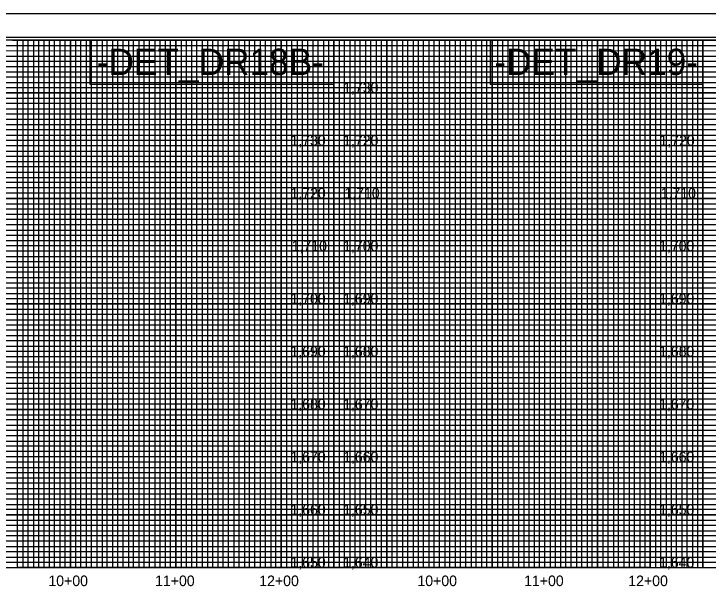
# Model space of a CAD drawing. Extents: x 505692 to 527456, y 415959 to 439886.
# Drawn here: x 506355 to 507014, y 439315 to 439861 of the extents above; entities that cross this region are included whole.
import ezdxf

# ---------------------------------------------------------------- set-up
doc = ezdxf.new("R2010")
doc.units = 0
for name, color, linetype in [('Exist Vertical Profile Vertical Axis Label', 7, 'Continuous'), ('Old_Level_1', 7, 'Continuous'), ('Prop Grid Mask', 7, 'Continuous'), ('Sheet Cutting Line CELL', 7, 'Continuous'), ('Sheet DOT Grid CELL', 7, 'Continuous'), ('Sheet Layout Profile Border Port 1', 7, 'Continuous'), ('Sheet Layout Profile Border Port 2', 7, 'Continuous'), ('Sheet Plot Border Inside CELL', 7, 'Continuous'), ('Sheet Plot Border Outside CELL', 7, 'Continuous'), ('Sheet Profile CELL', 7, 'Continuous'), ('Sheet Profile Grid Major CELL', 7, 'Continuous'), ('Sheet Profile Grid Middle CELL', 7, 'Continuous'), ('Sheet Profile Grid Minor CELL', 7, 'Continuous')]:
    doc.layers.add(name, color=color, linetype=linetype)

msp = doc.modelspace()

# ---------------------------------------------------------------- linework, layer by layer
at = {"layer": 'Prop Grid Mask'}
for points in [[(506658.68, 439836.14), (506427.08, 439836.14), (506427.08, 439794.44), (506658.68, 439794.44)], [(507008.68, 439836.14), (506806.91, 439836.14), (506806.91, 439794.44), (507008.68, 439794.44)]]:
    msp.add_lwpolyline(points, close=True, dxfattribs=at)
at = {"layer": 'Sheet Cutting Line CELL'}
msp.add_line((507375.68, 439861.14), (505691.68, 439861.14), dxfattribs=at)
at = {"layer": 'Sheet DOT Grid CELL'}
for p, q in [((506358.68, 439336.14), (506358.68, 439836.14)), ((506408.68, 439336.14), (506408.68, 439836.14)), ((506458.68, 439336.14), (506458.68, 439836.14)), ((506508.68, 439336.14), (506508.68, 439836.14)), ((506558.68, 439336.14), (506558.68, 439836.14)), ((506608.68, 439336.14), (506608.68, 439836.14)), ((506658.68, 439336.14), (506658.68, 439836.14)), ((506708.68, 439336.14), (506708.68, 439836.14)), ((506758.68, 439336.14), (506758.68, 439836.14)), ((506808.68, 439336.14), (506808.68, 439836.14)), ((506858.68, 439336.14), (506858.68, 439836.14)), ((506908.68, 439336.14), (506908.68, 439836.14)), ((506958.68, 439336.14), (506958.68, 439836.14)), ((507008.68, 439336.14), (507008.68, 439836.14)), ((507158.63, 439786.14), (505858.68, 439786.14)), ((507158.63, 439736.14), (505858.68, 439736.14)), ((507158.68, 439686.14), (505858.68, 439686.14)), ((507358.68, 439636.14), (505858.68, 439636.14)), ((507358.68, 439586.14), (505858.68, 439586.14)), ((507358.68, 439536.14), (505858.68, 439536.14)), ((507358.68, 439486.14), (505858.68, 439486.14)), ((507358.68, 439436.14), (505858.68, 439436.14)), ((507358.68, 439386.14), (505858.68, 439386.14))]:
    msp.add_line(p, q, dxfattribs=at)
at = {"layer": 'Sheet Layout Profile Border Port 1'}
msp.add_lwpolyline([(506708.68, 439836.14), (506958.68, 439836.14), (506958.68, 439336.14), (506708.68, 439336.14)], close=True, dxfattribs=at)
at = {"layer": 'Sheet Layout Profile Border Port 2'}
msp.add_lwpolyline([(506358.68, 439836.14), (506708.68, 439836.14), (506708.68, 439336.14), (506358.68, 439336.14)], close=True, dxfattribs=at)
at = {"layer": 'Sheet Plot Border Inside CELL'}
msp.add_lwpolyline([(505704.68, 438783.59), (507371.18, 438783.59), (507371.18, 439838.69), (505704.68, 439838.69)], close=True, dxfattribs=at)
at = {"layer": 'Sheet Plot Border Outside CELL'}
msp.add_lwpolyline([(505691.68, 438761.14), (507375.68, 438761.14), (507375.68, 439861.14), (505691.68, 439861.14)], close=True, dxfattribs=at)
at = {"layer": 'Sheet Profile CELL'}
for p, q in [((506658.68, 439836.14), (506658.68, 439336.14)), ((507008.68, 439836.14), (507008.68, 439336.14)), ((505858.68, 439336.14), (507358.68, 439336.14))]:
    msp.add_line(p, q, dxfattribs=at)
msp.add_lwpolyline([(507358.68, 439836.14), (505858.68, 439836.14), (505858.68, 438786.14), (507358.68, 438786.14)], close=True, dxfattribs=at)
at = {"layer": 'Sheet Profile Grid Major CELL'}
for points in [[(506308.68, 439336.14), (506358.68, 439336.14), (506358.68, 439836.14), (506408.68, 439836.14), (506408.68, 439336.14), (506458.68, 439336.14), (506458.68, 439836.14), (506508.68, 439836.14), (506508.68, 439336.14), (506558.68, 439336.14), (506558.68, 439836.14), (506608.68, 439836.14), (506608.68, 439336.14), (506658.68, 439336.14), (506658.68, 439836.14), (506708.68, 439836.14), (506708.68, 439336.14), (506758.68, 439336.14), (506758.68, 439836.14), (506808.68, 439836.14), (506808.68, 439336.14), (506858.68, 439336.14), (506858.68, 439836.14), (506908.68, 439836.14), (506908.68, 439336.14), (506958.68, 439336.14), (506958.68, 439836.14), (507008.68, 439836.14), (507008.68, 439336.14), (507058.68, 439336.14)], [(505858.68, 439786.14), (507158.68, 439786.14)], [(507158.68, 439736.14), (505858.68, 439736.14), (505858.68, 439686.14), (507158.68, 439686.14)], [(507358.68, 439636.14), (505858.68, 439636.14), (505858.68, 439586.14), (507358.68, 439586.14)], [(507358.68, 439536.14), (505858.68, 439536.14), (505858.68, 439486.14), (507358.68, 439486.14)], [(507358.68, 439436.14), (505858.68, 439436.14), (505858.68, 439436.14), (505858.68, 439386.14), (507358.68, 439386.14)]]:
    msp.add_lwpolyline(points, dxfattribs=at)
at = {"layer": 'Sheet Profile Grid Middle CELL'}
msp.add_line((505858.68, 439811.14), (507158.63, 439811.14), dxfattribs=at)
for points in [[(506333.68, 439336.14), (506383.68, 439336.14), (506383.68, 439836.14), (506433.68, 439836.14), (506433.68, 439336.14), (506483.68, 439336.14), (506483.68, 439336.14), (506483.68, 439836.14), (506533.68, 439836.14), (506533.68, 439336.14), (506583.68, 439336.14), (506583.68, 439836.14), (506633.68, 439836.14), (506633.68, 439336.14), (506683.68, 439336.14), (506683.68, 439836.14), (506733.68, 439836.14), (506733.68, 439336.14), (506783.68, 439336.14), (506783.68, 439836.14), (506833.68, 439836.14), (506833.68, 439336.14), (506883.68, 439336.14), (506883.68, 439836.14), (506933.68, 439836.14), (506933.68, 439336.14), (506983.68, 439336.14), (506983.68, 439836.14), (507033.68, 439836.14)], [(507158.68, 439761.14), (505858.68, 439761.14), (505858.68, 439711.14), (507158.68, 439711.14)], [(507358.68, 439661.14), (505858.68, 439661.14), (505858.68, 439611.14), (507183.68, 439611.14)], [(507358.68, 439561.14), (505858.68, 439561.14), (505858.68, 439511.14), (507358.68, 439511.14)], [(507358.68, 439461.14), (505858.68, 439461.14), (505858.68, 439411.14), (507358.68, 439411.14)], [(507358.68, 439361.14), (505858.68, 439361.14)]]:
    msp.add_lwpolyline(points, dxfattribs=at)
at = {"layer": 'Sheet Profile Grid Minor CELL'}
for p, q in [((505908.68, 439831.14), (507158.68, 439831.14)), ((507158.68, 439826.14), (505908.68, 439825.79)), ((505908.68, 439821.14), (507158.68, 439821.14)), ((507158.63, 439701.14), (505908.68, 439701.14)), ((507158.68, 439696.14), (505908.68, 439696.14)), ((507158.68, 439691.14), (505908.68, 439691.14)), ((505908.68, 439681.14), (507158.68, 439681.14)), ((507158.68, 439676.14), (505908.68, 439676.14)), ((505908.68, 439671.14), (507308.68, 439671.14)), ((507308.68, 439651.14), (505908.68, 439651.14)), ((505908.68, 439646.14), (507308.68, 439646.14)), ((507308.68, 439626.14), (505908.68, 439626.14)), ((505908.68, 439621.14), (507308.68, 439621.14)), ((507308.68, 439601.14), (505908.68, 439601.14)), ((505908.68, 439596.14), (507308.68, 439596.14)), ((507308.68, 439591.14), (505908.68, 439591.14)), ((505908.68, 439581.14), (507308.68, 439581.14)), ((507308.68, 439576.14), (505908.68, 439576.14)), ((505908.68, 439571.14), (507308.68, 439571.14)), ((507308.68, 439566.14), (505908.68, 439566.14)), ((505908.68, 439556.14), (507308.68, 439556.14)), ((507308.68, 439551.14), (505908.68, 439551.14)), ((505908.68, 439546.14), (507308.68, 439546.14)), ((507308.68, 439541.14), (505908.68, 439541.14)), ((505908.68, 439531.14), (507308.68, 439531.14)), ((507308.68, 439526.14), (505908.68, 439526.14)), ((505908.68, 439521.14), (507308.68, 439521.14)), ((507308.68, 439516.14), (505908.68, 439516.14)), ((505908.68, 439506.14), (507308.68, 439506.14)), ((507308.68, 439501.14), (505908.68, 439501.14)), ((505908.68, 439496.14), (507308.68, 439496.14)), ((507308.68, 439491.14), (505908.68, 439491.14)), ((505908.68, 439481.14), (507308.68, 439481.14)), ((507308.68, 439476.14), (505908.68, 439476.14)), ((505908.68, 439471.14), (507308.68, 439471.14)), ((507308.68, 439466.14), (505908.68, 439466.14)), ((505908.68, 439456.14), (507308.68, 439456.14)), ((507308.68, 439451.14), (505908.68, 439451.14)), ((507308.68, 439446.14), (505908.68, 439446.14)), ((507308.68, 439441.14), (505908.68, 439441.14)), ((505908.68, 439431.14), (507308.68, 439431.14)), ((507308.68, 439426.14), (505908.68, 439426.14)), ((505908.68, 439421.14), (507308.68, 439421.14)), ((507308.68, 439416.14), (505908.68, 439416.14)), ((505908.68, 439406.14), (507308.68, 439406.14)), ((507308.68, 439401.14), (505908.68, 439401.14)), ((505908.68, 439396.14), (507308.68, 439396.14)), ((507308.68, 439391.14), (505908.68, 439391.14)), ((505908.68, 439381.14), (507308.68, 439381.14)), ((507308.68, 439376.14), (505908.68, 439376.14)), ((505908.68, 439371.14), (507308.68, 439371.14)), ((507308.68, 439366.14), (505908.68, 439366.14)), ((505908.68, 439356.14), (507308.68, 439356.14)), ((507308.68, 439351.14), (505908.68, 439351.14)), ((505908.68, 439346.14), (507308.68, 439346.14))]:
    msp.add_line(p, q, dxfattribs=at)
for points in [[(506353.68, 439836.14), (506363.68, 439836.14), (506363.68, 439336.14), (506368.68, 439336.14), (506368.68, 439836.14), (506373.68, 439836.14), (506373.68, 439336.14), (506378.68, 439336.14), (506378.68, 439836.14), (506388.68, 439836.14), (506388.68, 439336.14), (506393.68, 439336.14), (506393.68, 439836.14), (506398.68, 439836.14), (506398.68, 439336.14), (506403.68, 439336.14), (506403.68, 439836.14), (506413.68, 439836.14), (506413.68, 439336.14), (506418.68, 439336.14), (506418.68, 439836.14), (506423.68, 439836.14), (506423.68, 439336.14), (506428.68, 439336.14), (506428.68, 439836.14), (506438.68, 439836.14)], [(506438.68, 439836.14), (506438.68, 439336.14), (506443.68, 439336.14), (506443.68, 439836.14), (506448.68, 439836.14), (506448.68, 439336.14), (506453.68, 439336.14), (506453.68, 439836.14), (506463.68, 439836.14), (506463.68, 439336.14), (506468.68, 439336.14), (506468.68, 439836.14), (506473.68, 439836.14), (506473.68, 439336.14), (506478.68, 439336.14), (506478.68, 439836.14), (506488.68, 439836.14), (506488.68, 439336.14), (506493.68, 439336.14), (506493.68, 439836.14), (506498.68, 439836.14), (506498.68, 439336.14), (506503.68, 439336.14), (506503.68, 439836.14), (506513.68, 439836.14), (506513.68, 439336.14), (506518.68, 439336.14), (506518.68, 439836.14), (506523.68, 439836.14), (506523.68, 439336.14), (506528.68, 439336.14), (506528.68, 439836.14), (506538.68, 439836.14), (506538.68, 439336.14), (506543.68, 439336.14), (506543.68, 439836.14), (506548.68, 439836.14), (506548.68, 439336.14), (506553.68, 439336.14), (506553.68, 439836.14), (506563.68, 439836.14), (506563.68, 439336.14), (506563.68, 439336.14), (506568.68, 439336.14), (506568.68, 439836.14), (506573.68, 439836.14), (506573.68, 439336.14), (506578.68, 439336.14), (506578.68, 439836.14), (506588.68, 439836.14), (506588.68, 439336.14), (506593.68, 439336.14), (506593.68, 439836.14), (506598.68, 439836.14), (506598.68, 439336.14), (506603.68, 439336.14), (506603.68, 439836.14), (506613.68, 439836.14), (506613.68, 439336.14), (506618.68, 439336.14), (506618.68, 439836.14), (506623.68, 439836.14), (506623.68, 439336.14), (506628.68, 439336.14), (506628.68, 439836.14), (506638.68, 439836.14), (506638.68, 439336.14), (506643.68, 439336.14), (506643.68, 439836.14), (506648.68, 439836.14), (506648.68, 439336.14), (506653.68, 439336.14), (506653.68, 439836.14), (506663.68, 439836.14), (506663.68, 439336.14), (506668.68, 439336.14), (506668.68, 439836.14), (506673.68, 439836.14), (506673.68, 439336.14), (506678.68, 439336.14), (506678.68, 439836.14), (506688.68, 439836.14), (506688.68, 439336.14), (506693.68, 439336.14), (506693.68, 439836.14), (506698.68, 439836.14), (506698.68, 439336.14), (506703.68, 439336.14), (506703.68, 439836.14), (506713.68, 439836.14), (506713.68, 439336.14), (506717.37, 439336.14), (506718.68, 439336.14), (506718.68, 439836.14), (506723.68, 439836.14), (506723.68, 439336.14), (506728.68, 439336.14), (506728.68, 439836.14), (506738.68, 439836.14), (506738.68, 439336.14), (506743.68, 439336.14)], [(506743.68, 439336.14), (506743.68, 439836.14), (506748.68, 439836.14), (506748.68, 439336.14), (506753.68, 439336.14), (506753.68, 439836.14), (506763.68, 439836.14), (506763.68, 439336.14), (506768.68, 439336.14), (506768.68, 439836.14), (506773.68, 439836.14), (506773.68, 439336.14), (506778.68, 439336.14), (506778.68, 439836.14), (506788.68, 439836.14), (506788.68, 439336.14), (506793.68, 439336.14), (506793.68, 439836.14), (506798.68, 439836.14), (506798.68, 439336.14), (506803.68, 439336.14), (506803.68, 439836.14), (506813.68, 439836.14), (506813.68, 439336.14), (506818.68, 439336.14), (506818.68, 439836.14), (506823.68, 439836.14), (506823.68, 439336.14), (506828.68, 439336.14), (506828.68, 439836.14), (506838.68, 439836.14), (506838.68, 439336.14), (506843.68, 439336.14), (506843.68, 439836.14), (506848.68, 439836.14), (506848.68, 439336.14), (506853.68, 439336.14), (506853.68, 439836.14), (506863.68, 439836.14), (506863.68, 439336.14), (506868.68, 439336.14), (506868.68, 439836.14), (506873.68, 439836.14), (506873.68, 439336.14), (506878.68, 439336.14), (506878.68, 439836.14), (506888.68, 439836.14), (506888.68, 439336.14), (506893.68, 439336.14), (506893.68, 439836.14), (506898.68, 439836.14), (506898.68, 439336.14), (506903.68, 439336.14), (506903.68, 439836.14), (506913.68, 439836.14), (506913.68, 439336.14), (506918.68, 439336.14), (506918.68, 439836.14), (506923.68, 439836.14), (506923.68, 439336.14), (506928.68, 439336.14), (506928.68, 439836.14), (506938.68, 439836.14), (506938.68, 439336.14), (506943.68, 439336.14), (506943.68, 439836.14), (506948.68, 439836.14), (506948.68, 439336.14), (506953.68, 439336.14), (506953.68, 439836.14), (506963.68, 439836.14), (506963.68, 439336.14), (506968.68, 439336.14), (506968.68, 439836.14), (506973.68, 439836.14), (506973.68, 439336.14), (506978.68, 439336.14), (506978.68, 439836.14), (506988.68, 439836.14), (506988.68, 439336.14), (506993.68, 439336.14), (506993.68, 439836.14), (506998.68, 439836.14), (506998.68, 439336.14), (507003.68, 439336.14), (507003.68, 439836.14), (507013.68, 439836.14)], [(507158.68, 439816.14), (505908.68, 439816.14), (505908.68, 439806.14), (507158.68, 439806.14)], [(507158.63, 439801.14), (505908.68, 439801.14), (505908.68, 439796.14), (507158.68, 439796.14)], [(507158.68, 439791.14), (505908.68, 439791.14), (505908.68, 439781.14), (507158.68, 439781.14)], [(507158.68, 439776.14), (505908.68, 439776.14), (505908.68, 439771.14), (507158.68, 439771.14)], [(507158.68, 439766.14), (505908.68, 439766.14), (505908.68, 439756.14), (507158.68, 439756.14)], [(507158.68, 439751.14), (505908.68, 439751.14), (505908.68, 439746.14), (507158.68, 439746.14)], [(507158.68, 439741.14), (505908.68, 439741.14), (505908.68, 439731.14), (507158.68, 439731.14)], [(507158.68, 439726.04), (505908.78, 439726.04), (505908.78, 439721.14), (507158.68, 439721.14)], [(507158.68, 439716.14), (505908.68, 439716.14), (505908.68, 439706.14), (507158.68, 439706.14)], [(507308.68, 439666.14), (505908.68, 439666.14), (505908.68, 439656.14), (507308.68, 439656.14)], [(507308.68, 439641.14), (505908.68, 439641.14), (505908.68, 439631.14), (507308.68, 439631.14)], [(507308.68, 439616.14), (505908.68, 439616.14), (505908.68, 439606.14), (507308.68, 439606.14)], [(507308.68, 439341.14), (505908.68, 439341.14)]]:
    msp.add_lwpolyline(points, dxfattribs=at)

# ---------------------------------------------------------------- texts
at = {"layer": 'Exist Vertical Profile Vertical Axis Label'}
for s, p in [('1,730', (506667.37, 439786.14)), ('1,730', (506617.37, 439736.14)), ('1,720', (506667.37, 439736.14)), ('1,720', (506967.37, 439736.14)), ('1,720', (506617.37, 439686.14)), ('1,710', (506668.57, 439686.14)), ('1,710', (506968.57, 439686.14)), ('1,710', (506618.57, 439636.14)), ('1,700', (506667.37, 439636.14)), ('1,700', (506967.04, 439636.14)), ('1,700', (506617.37, 439586.14)), ('1,690', (506667.37, 439586.14)), ('1,690', (506967.04, 439586.14)), ('1,690', (506617.37, 439536.14)), ('1,680', (506667.37, 439536.14)), ('1,680', (506967.04, 439536.14)), ('1,680', (506617.37, 439486.14)), ('1,670', (506667.37, 439486.14)), ('1,670', (506967.04, 439486.14)), ('1,670', (506617.37, 439436.14)), ('1,660', (506667.37, 439436.14)), ('1,660', (506967.04, 439436.14)), ('1,660', (506617.37, 439386.14)), ('1,650', (506667.37, 439386.14)), ('1,650', (506967.04, 439386.14)), ('1,650', (506617.37, 439336.14)), ('1,640', (506667.37, 439336.14)), ('1,640', (506967.04, 439336.14)), ('10+00', (506387.81, 439318.64)), ('11+00', (506489, 439318.64)), ('12+00', (506587.81, 439318.64)), ('10+00', (506737.81, 439318.64)), ('11+00', (506839, 439318.64)), ('12+00', (506937.81, 439318.64))]:
    msp.add_text(s, height=10, dxfattribs=at).set_placement(p)
at = {"layer": 'Old_Level_1'}
for s, p in [('-DET_DR18B-', (506433.68, 439803.11)), ('-DET_DR19-', (506810.76, 439803.11))]:
    msp.add_text(s, height=25, dxfattribs=at).set_placement(p)

doc.saveas('drawing.dxf')
